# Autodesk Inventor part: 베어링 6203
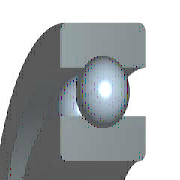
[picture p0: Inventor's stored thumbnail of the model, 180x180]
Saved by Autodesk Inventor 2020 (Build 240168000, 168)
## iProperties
IsCustomPart: 1
Created: 2015-09
Part Number: 베어링 6203
Material: 강철, 연강
Description: 깊은 그루브 볼 베어링
Document SubType Name: Modeling
Standard: KS B 2023
Standards Organization: KS
Language: ko-KR
Size Designation: 6203 - 17 x 40 x 12
Categories: <MemberInstance><Categories><Category DisplayName="샤프트 부품" InternalName="7f7aeb1f-a693-4053-b835-cee3144e0d98" Mnemonic="SHFT"><Category DisplayName="베어링" Inter
Density: 7.86 g/cm^3
Mass: 64.9809 g
Surface Area: 64.3582 cm^2
Volume: 8.26729 cm^3
Appearance: 노란색
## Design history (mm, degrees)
sketch "스케치" dims "d0" = 5.98 (= -0.26 x WD + 0.26 x BD)
  geometry: L1 (3.01, 14.25)-(8.99, 14.25); L2 (6, 14.25)-(6, 11.26); L3 (6, 14.25)-(6, 17.24); L4 (3.778, 12.249)-(0, 12.249); L5 (0, 8.5)-(12, 8.5); L6 (3.778, 16.251)-(0, 16.251); L7 (0, 20)-(12, 20); L8 (12, 8.5)-(12, 12.249); L9 (8.222, 12.249)-(12, 12.249); L10 (8.222, 16.251)-(12, 16.251); L11 (12, 20)-(12, 16.251); L12 (-1.4, 0)-(8.4, 0) reference; L13 (0, -0.3)-(0, 5.3) reference
  constraints: 22 end point, 4 point on line, 2 collinear, 2 perpendicular, 2 symmetric about line, 1 midpoint, 1 parallel, 14 other
  dimensions: "d9" = 17 diameter of L5 L12 (= WD); "d11" = 40 diameter of L7 L12 (= BD); "d12" = 12 distance between parallel lines of L8 L13 (= KB); "d13" = 24.498 diameter of L9 L12 (= 0.326 x BD + 0.674 x WD)
revolve "본체" stored, may be unused: angle "d6" = 90 deg
revolve "볼" stored, may be unused: angle "d7" = 90 deg
pattern_circular "IDS_ARRAYBALL[SIMPL:T]" dims angle "d3" = 360 deg
body "Solid1"
fillet "모깎기1" dims "d1" = 0.6 (= KRS)
other parameters: "WD" = 17 [user parameter; used in 5 equation terms], "BD" = 40 [user parameter; used in 5 equation terms], "KB" = 12 [user parameter; used in 1 equation term], "KRS" = 0.6 [user parameter; used in 1 equation term], "d4" = 0, "d5" = 0, "d8" = 0, "d14" = 0, "d15" = 0, "BBA" = 0 [user parameter], "BC0" = 4750000 [user parameter], "BC" = 9560000 [user parameter], "WR" = 8.5 (= 0.5 x WD) [user parameter]
